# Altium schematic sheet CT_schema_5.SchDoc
size 430 x 429 mm
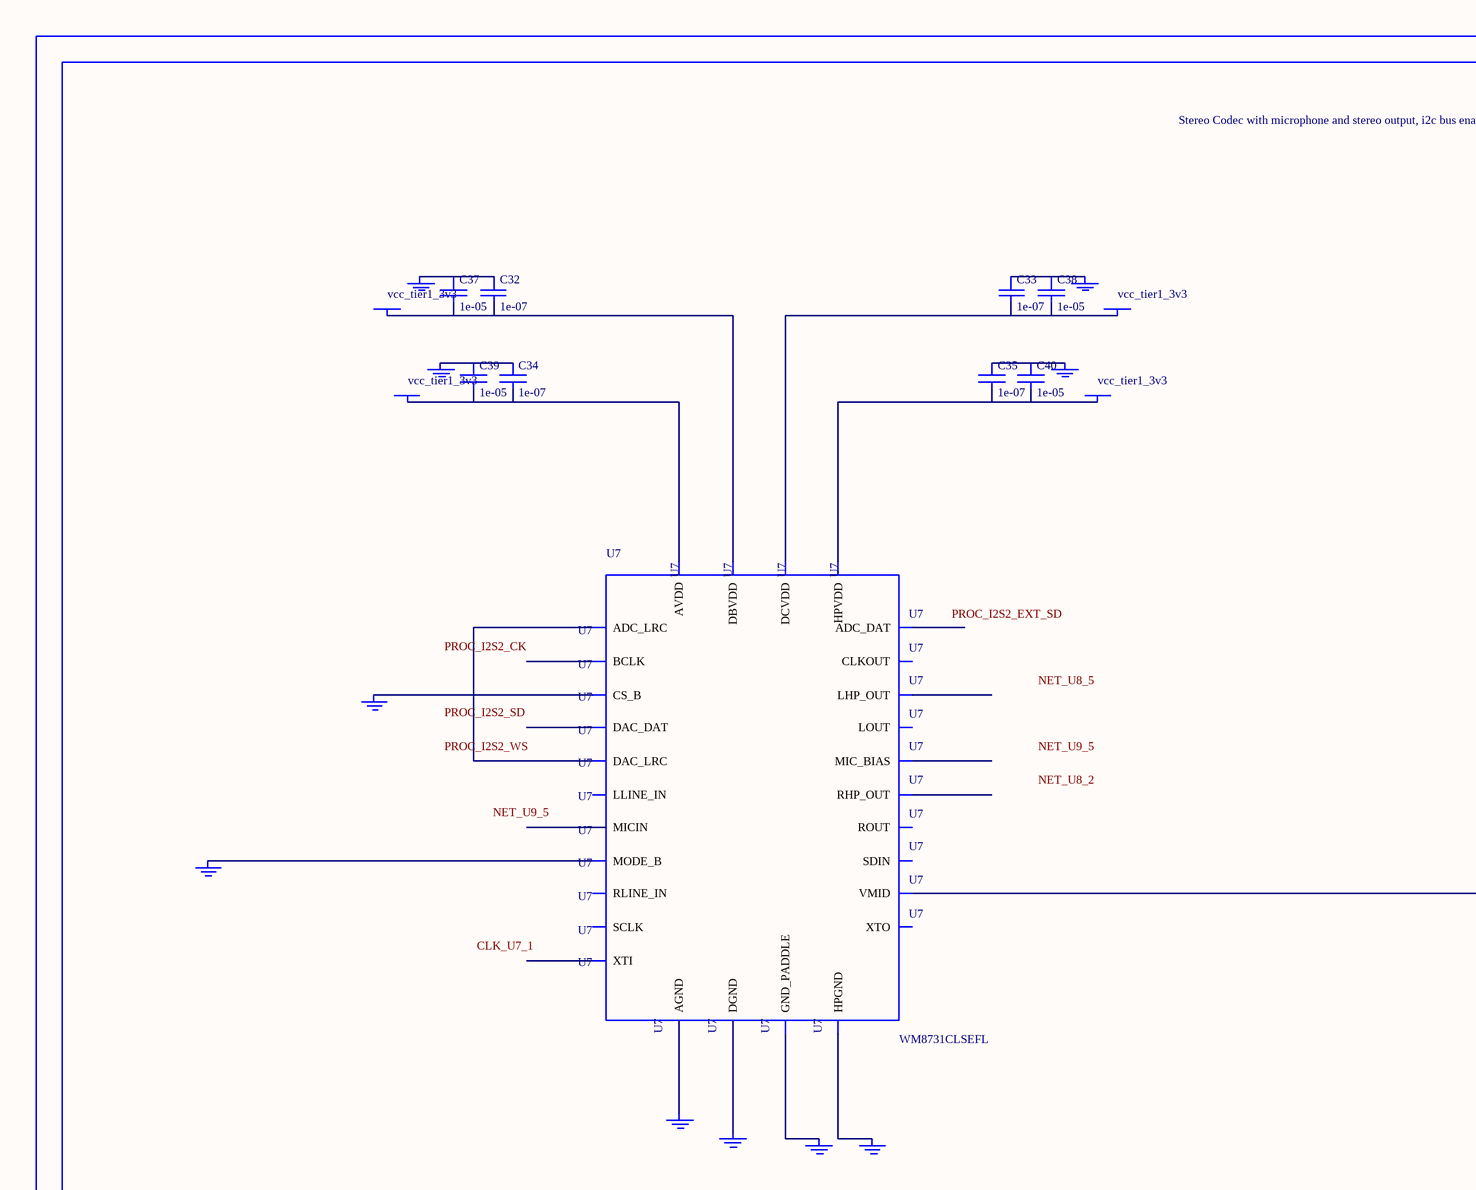
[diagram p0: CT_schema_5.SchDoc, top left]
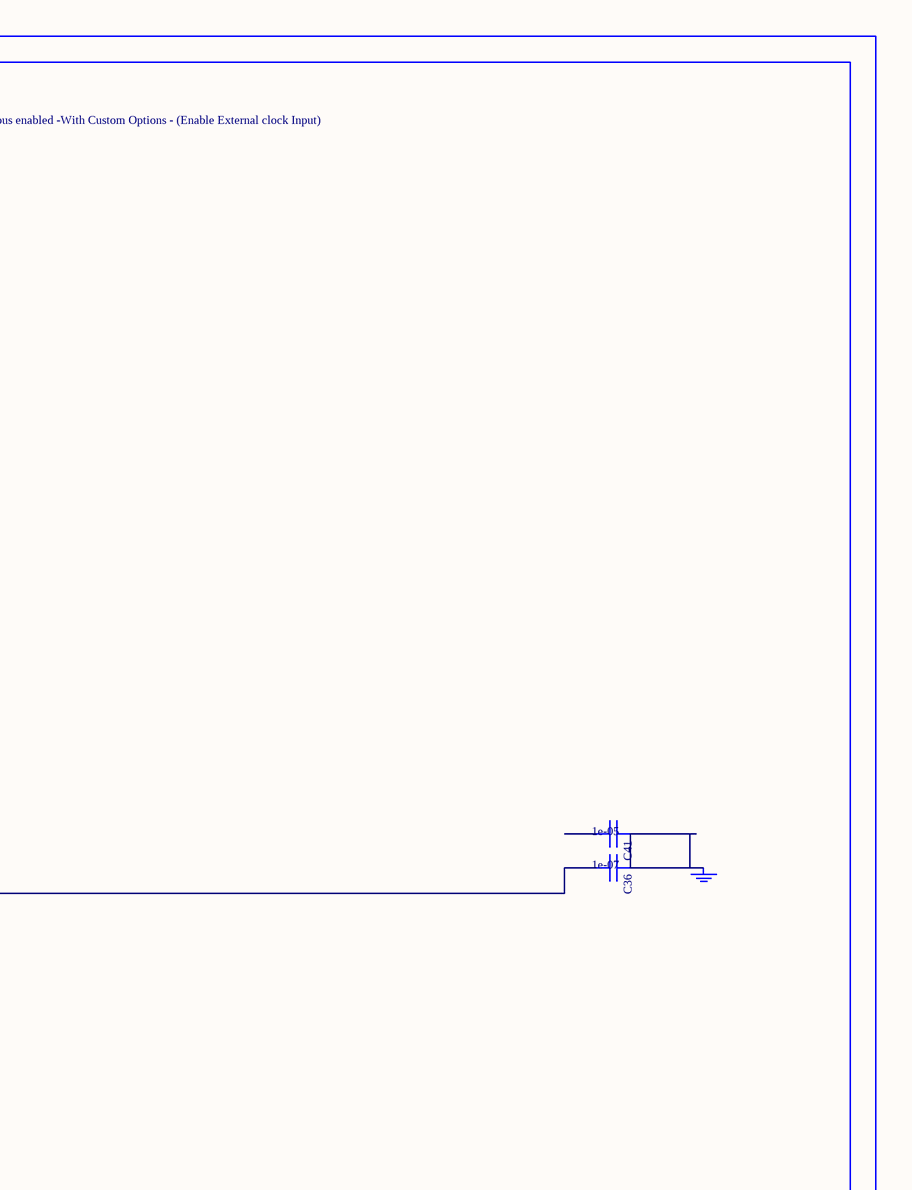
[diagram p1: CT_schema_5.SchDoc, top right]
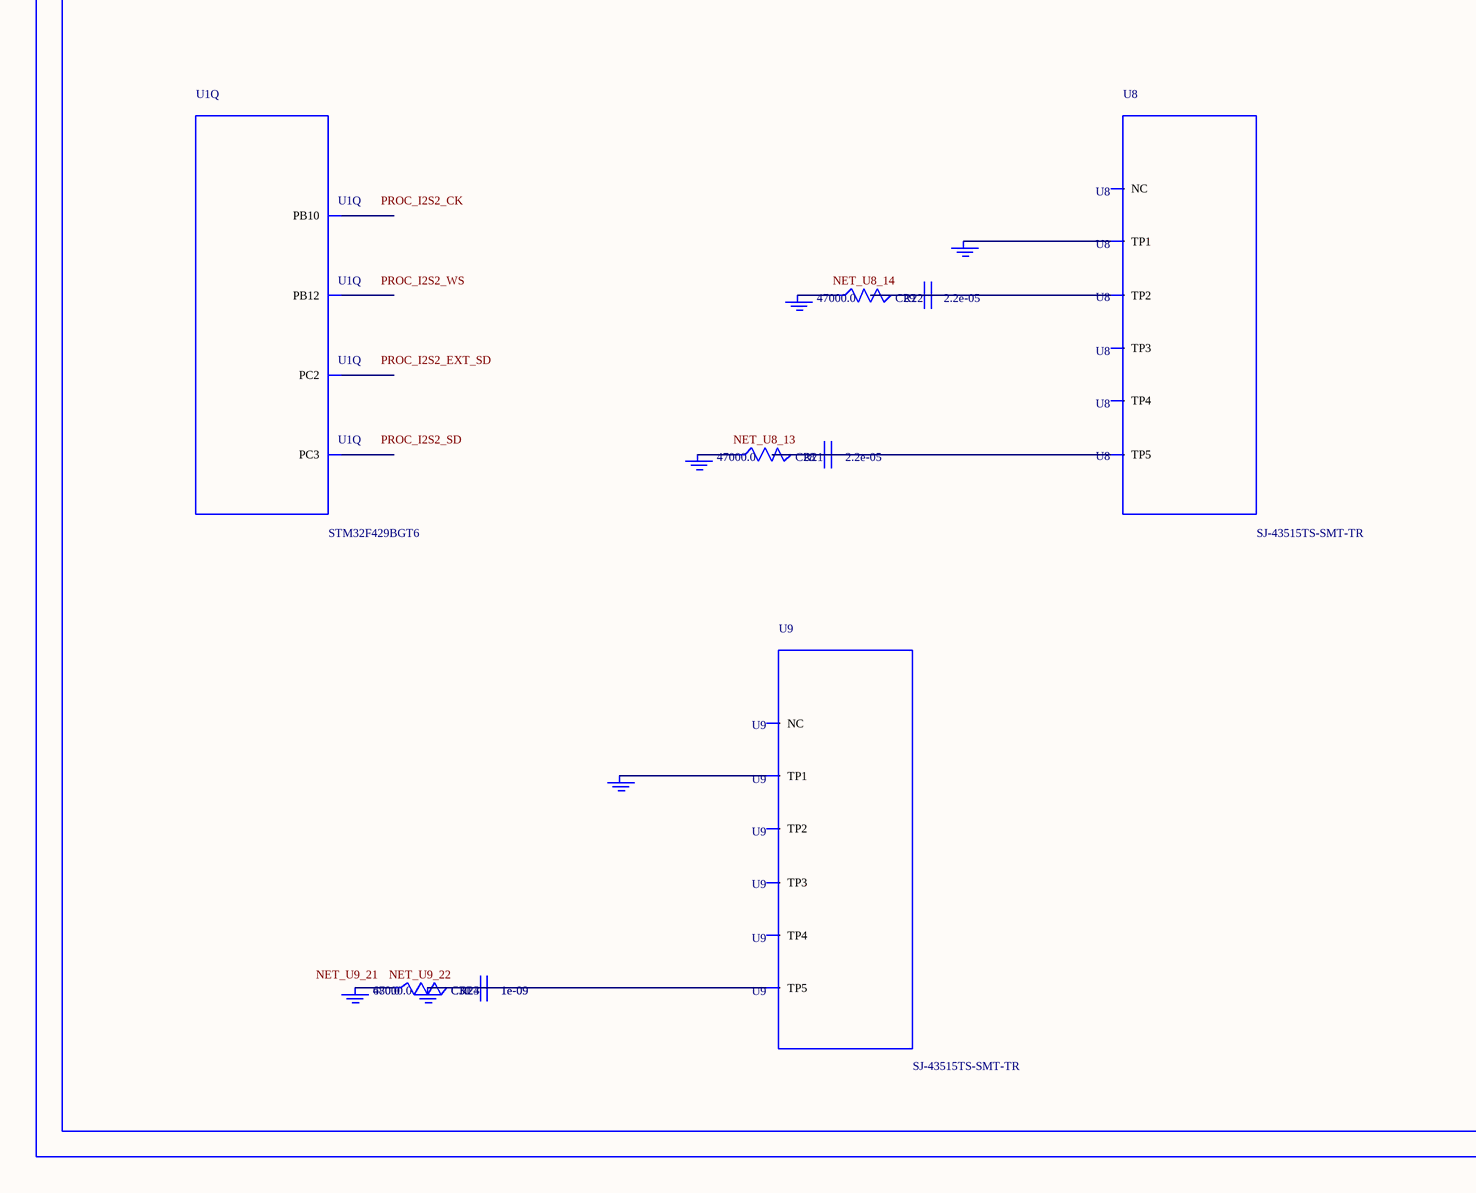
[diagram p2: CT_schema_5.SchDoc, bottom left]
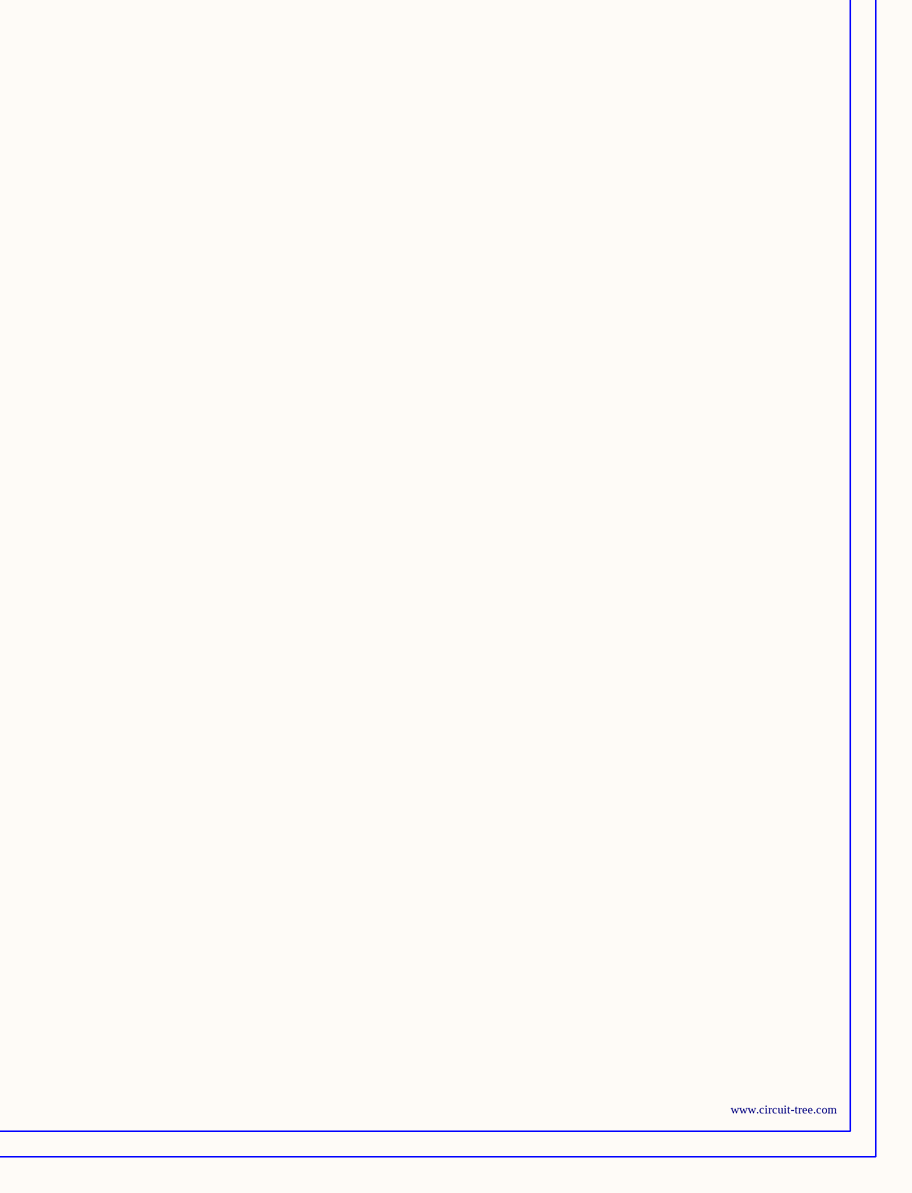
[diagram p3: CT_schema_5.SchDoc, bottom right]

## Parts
BORDER4  (no value)
C28  2.2e-05  [C1210]
C29  2.2e-05  [C1210]
C30  1e-09  [C0402]
C31  1e-09  [C0402]
C32  1e-07  [C0402]
C33  1e-07  [C0402]
C34  1e-07  [C0402]
C35  1e-07  [C0402]
C36  1e-07  [C0402]
C37  1e-05  [C0805]
C38  1e-05  [C0805]
C39  1e-05  [C0805]
C40  1e-05  [C0805]
C41  1e-05  [C0805]
GND_INSTANCE_4_0  (no value)
GND_INSTANCE_4_1  (no value)
GND_INSTANCE_4_2  (no value)
GND_INSTANCE_4_3  (no value)
GND_INSTANCE_4_4  (no value)
GND_INSTANCE_4_5  (no value)
GND_INSTANCE_4_6  (no value)
GND_INSTANCE_4_7  (no value)
GND_INSTANCE_4_8  (no value)
GND_INSTANCE_4_9  (no value)
GND_INSTANCE_4_10  (no value)
GND_INSTANCE_4_11  (no value)
GND_INSTANCE_4_12  (no value)
GND_INSTANCE_4_13  (no value)
GND_INSTANCE_4_14  (no value)
GND_INSTANCE_4_15  (no value)
GND_INSTANCE_4_16  (no value)
POWER_INSTANCE_4_0  vcc_tier1_3v3
POWER_INSTANCE_4_1  vcc_tier1_3v3
POWER_INSTANCE_4_2  vcc_tier1_3v3
POWER_INSTANCE_4_3  vcc_tier1_3v3
R21  47000.0  [R0603]
R22  47000.0  [R0603]
R23  47000.0  [R0603]
R24  680.0  [R0603]
U1  STM32F429BGT6  [LQFP208]  (part Q of 17)
U7  WM8731CLSEFL  [QFN-28]
U8  SJ-43515TS-SMT-TR  [SJ-43515TS-SMT-TR]
U9  SJ-43515TS-SMT-TR  [SJ-43515TS-SMT-TR]

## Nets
NetC28_1: C28.1 C28.2 R21.2 U8.5(TP5)
NetC29_1: C29.1 C29.2 R22.2 U8.2(TP2)
NetC30_1: C30.1 C30.2 C31.1 C31.2 GND_INSTANCE_4_16.0(GND) R23.2 R24.2 U9.5(TP5)
NetC32_1: C32.1 C37.1 GND_INSTANCE_4_1.0(GND)
NetC32_2: C32.2 C37.2 POWER_INSTANCE_4_1.0(PWR) U7.5(DBVDD)
NetC33_1: C33.1 C38.1 GND_INSTANCE_4_0.0(GND)
NetC33_2: C33.2 C38.2 POWER_INSTANCE_4_0.0(PWR) U7.3(DCVDD)
NetC34_1: C34.1 C39.1 GND_INSTANCE_4_4.0(GND)
NetC34_2: C34.2 C39.2 POWER_INSTANCE_4_3.0(PWR) U7.18(AVDD)
NetC35_1: C35.1 C40.1 GND_INSTANCE_4_2.0(GND)
NetC35_2: C35.2 C40.2 POWER_INSTANCE_4_2.0(PWR) U7.12(HPVDD)
NetC36_1: C36.1 C41.1 GND_INSTANCE_4_5.0(GND)
NetC36_2: C36.2 U7.20(VMID)
NetGND_INSTANCE_4_3_0: GND_INSTANCE_4_3.0(GND) U7.15(HPGND)
NetGND_INSTANCE_4_6_0: GND_INSTANCE_4_6.0(GND) U7.25(MODE_B)
NetGND_INSTANCE_4_7_0: GND_INSTANCE_4_7.0(GND) U7.26(CS_B)
NetGND_INSTANCE_4_8_0: GND_INSTANCE_4_8.0(GND) U7.29(GND_PADDLE)
NetGND_INSTANCE_4_9_0: GND_INSTANCE_4_9.0(GND) U7.4(DGND)
NetGND_INSTANCE_4_10_0: GND_INSTANCE_4_10.0(GND) U7.19(AGND)
NetGND_INSTANCE_4_11_0: GND_INSTANCE_4_11.0(GND) U8.1(TP1)
NetGND_INSTANCE_4_12_0: GND_INSTANCE_4_12.0(GND) R22.1
NetGND_INSTANCE_4_13_0: GND_INSTANCE_4_13.0(GND) R21.1
NetGND_INSTANCE_4_14_0: GND_INSTANCE_4_14.0(GND) U9.1(TP1)
NetGND_INSTANCE_4_15_0: GND_INSTANCE_4_15.0(GND) R23.1 R24.1
NetU7_9: U7.9(DAC_LRC) U7.11(ADC_LRC)

Not connected (* = marked no-connect by the designer): C41 2; U1 37(PC2) 38(PC3) 90(PB10) 104(PB12); U7 1(XTI) 2(XTO) 6(CLKOUT) 7(BCLK) 8(DAC_DAT) 10(ADC_DAT) 13(LHP_OUT) 14(RHP_OUT) 16(LOUT) 17(ROUT) 21(MIC_BIAS) 22(MICIN) 23(RLINE_IN) 24(LLINE_IN) 27(SDIN) 28(SCLK); U8 3(TP3) 4(TP4) 6(NC); U9 2(TP2) 3(TP3) 4(TP4) 6(NC)

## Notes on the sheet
- Labels drawn without touching a wire or pin: CLK_U7_1, NET_U8_2, NET_U8_5, NET_U8_13, NET_U8_14, NET_U9_5, NET_U9_21, NET_U9_22, PROC_I2S2_CK, PROC_I2S2_EXT_SD, PROC_I2S2_SD, PROC_I2S2_WS

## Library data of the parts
BORDER4 = BORDER_PAGE4
C28 C29 = C1210C224K5RACTU
C30 C31 = C0402C102K3RAC
C32-C36 = C0402C104K3RACTU
C37-C41 = C0805C106K8RACTU
GND_INSTANCE_4_0-GND_INSTANCE_4_16 = GND
POWER_INSTANCE_4_0-POWER_INSTANCE_4_3 = PWR
R21-R23 = RC0603JR-0747KL
R24 = RC0603JR-07680RL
